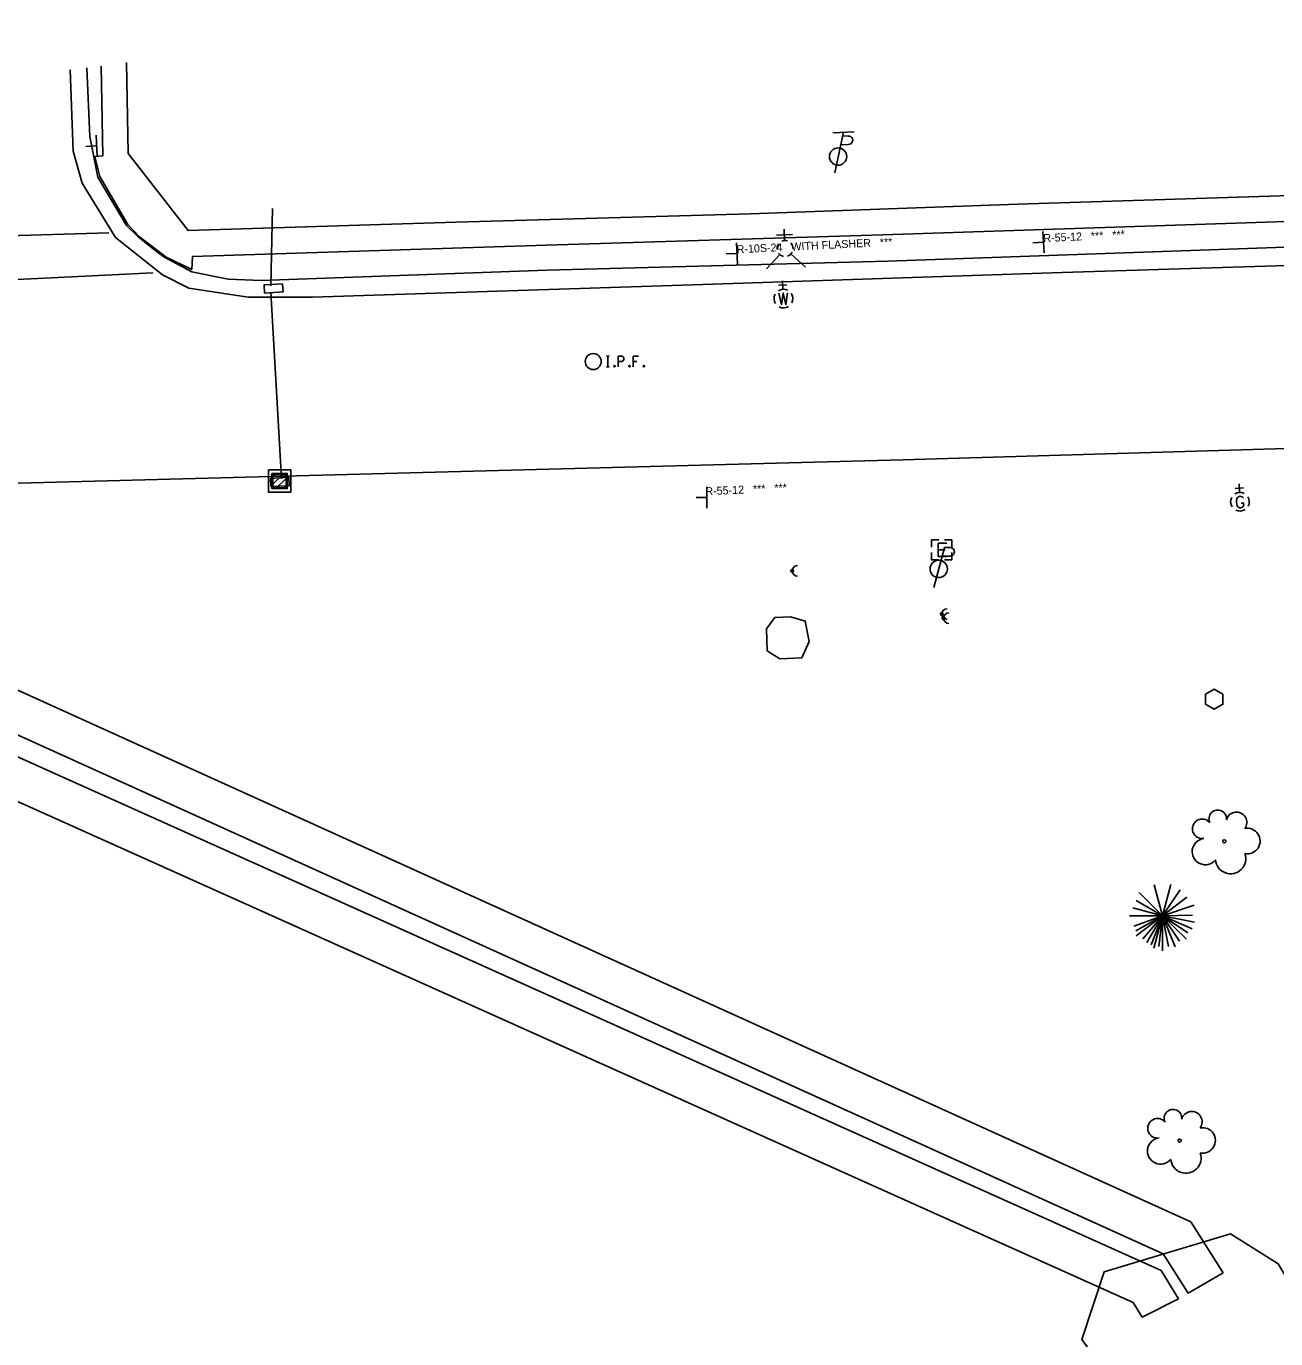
# Model space of a CAD drawing. Extents: x 129284 to 131418, y 268402 to 269012.
# Drawn here: x 129619.3 to 129806.6, y 268577.7 to 268774.5 of the extents above; entities that cross this region are included whole.
import ezdxf

# ---------------------------------------------------------------- set-up
doc = ezdxf.new("R2010")
doc.units = 0
for name, color, linetype in [('Default', 7, 'Continuous'), ('DR_X_Cells', 7, 'Continuous'), ('DR_X_Storm_Sewer', 7, 'Continuous'), ('GK_Drainage_Nodes', 7, 'Continuous'), ('Level 63', 7, 'Continuous'), ('PM_X_Crosswalk', 7, 'Continuous'), ('PV_X_Curb', 7, 'Continuous'), ('PV_X_EOP', 7, 'Continuous'), ('PV_X_Walk', 7, 'Continuous'), ('RD_X_Cells', 7, 'Continuous'), ('SN_X_Public', 7, 'Continuous'), ('SV_X_Mon_Cells_Found', 7, 'Continuous'), ('SV_X_Top_of_Bank', 7, 'Continuous'), ('UT_X_Electric_Cells', 7, 'Continuous'), ('UT_X_Gas', 7, 'Continuous'), ('UT_X_Misc_Cells', 7, 'Continuous'), ('VG_X_Cells', 7, 'Continuous')]:
    doc.layers.add(name, color=color, linetype=linetype)

# ---------------------------------------------------------------- blocks, each defined once
blk = doc.blocks.new('POINT_DISPLAY')
at = {"layer": 'Default'}
blk.add_line((0, 0), (0, 0), dxfattribs=at)

msp = doc.modelspace()

# ---------------------------------------------------------------- linework, layer by layer
at = {"layer": 'DR_X_Cells'}
for p, q in [((129656.14, 268705.67), (129657.9, 268707.43)), ((129656.14, 268706.8), (129656.77, 268707.43)), ((129656.74, 268705.14), (129658.43, 268706.83)), ((129657.87, 268705.14), (129658.43, 268705.7))]:
    msp.add_line(p, q, dxfattribs=at)
for points in [[(129655.62, 268707.95), (129658.95, 268707.95), (129658.95, 268704.61), (129655.62, 268704.61), (129655.62, 268707.95)], [(129656.14, 268707.43), (129658.43, 268707.43), (129658.43, 268705.14), (129656.14, 268705.14), (129656.14, 268707.43)], [(129656.29, 268707.28), (129658.29, 268707.28), (129658.29, 268705.28), (129656.29, 268705.28), (129656.29, 268707.28)]]:
    msp.add_lwpolyline(points, dxfattribs=at)
at = {"layer": 'DR_X_Storm_Sewer'}
for p, q in [((129602.83, 268681.77), (129793.89, 268595.19)), ((129789.73, 268590.4), (129598.55, 268677.03)), ((129597.05, 268674.32), (129789.44, 268587.88)), ((129785.23, 268583.1), (129592.78, 268669.57)), ((129793.89, 268595.19), (129798.76, 268587.53)), ((129793.49, 268584.48), (129789.73, 268590.4)), ((129789.44, 268587.88), (129792.03, 268583.64)), ((129798.76, 268587.53), (129793.49, 268584.48)), ((129786.59, 268580.89), (129785.23, 268583.1)), ((129792.03, 268583.64), (129786.59, 268580.89))]:
    msp.add_line(p, q, dxfattribs=at)
at = {"layer": 'PM_X_Crosswalk'}
for p, q in [((129596.24, 268742.49), (129631.69, 268743.48)), ((129638.28, 268737.49), (129590.12, 268735.16))]:
    msp.add_line(p, q, dxfattribs=at)
at = {"layer": 'PV_X_Curb'}
msp.add_lwpolyline([(129628.39, 268768.24), (129628.85, 268757.96), (129630.03, 268751.84), (129634.34, 268744.59), (129636.11, 268742.9), (129638.8, 268740.76), (129639.93, 268739.9), (129644.15, 268737.64), (129649.59, 268736.54), (129654.52, 268736.36), (129697.34, 268737.91), (129748.47, 268739.24), (129806.62, 268741.28), (129827.63, 268742.09), (129834.82, 268743.89), (129838.76, 268746.54), (129839.77, 268747.28), (129841.85, 268749.4), (129842.79, 268750.35), (129845.39, 268754.56), (129847.27, 268759.97), (129849.06, 268773.91)], dxfattribs=at)
at = {"layer": 'PV_X_EOP'}
msp.add_lwpolyline([(129851.57, 268773.49), (129849.39, 268758.43), (129846.3, 268751.07), (129843.04, 268746.84), (129839.56, 268743.92), (129834.27, 268741.14), (129825.93, 268739.15), (129774.6, 268737.57), (129719.24, 268735.72), (129662.21, 268733.87), (129652.57, 268733.86), (129643.67, 268735.18), (129639.72, 268737.19), (129632.68, 268742.79), (129627.69, 268750.93), (129626.36, 268755.75), (129625.89, 268767.95)], dxfattribs=at)
at = {"layer": 'PV_X_Walk'}
for p, q in [((129629.86, 268756.53), (129628.26, 268756.46)), ((129629.86, 268756.53), (129628.26, 268756.46)), ((129629.86, 268756.53), (129628.26, 268756.46)), ((129629.78, 268758.13), (129629.94, 268754.94)), ((129629.78, 268758.13), (129629.94, 268754.94)), ((129629.78, 268758.13), (129629.94, 268754.94)), ((129771.73, 268743.68), (129771.89, 268740.49)), ((129771.73, 268743.68), (129771.89, 268740.49)), ((129771.73, 268743.68), (129771.89, 268740.49)), ((129725.76, 268742.02), (129725.92, 268738.82)), ((129725.76, 268742.02), (129725.92, 268738.82)), ((129725.76, 268742.02), (129725.92, 268738.82)), ((129771.81, 268742.09), (129770.21, 268742.01)), ((129771.81, 268742.09), (129770.21, 268742.01)), ((129771.81, 268742.09), (129770.21, 268742.01)), ((129725.84, 268740.42), (129724.24, 268740.34)), ((129725.84, 268740.42), (129724.24, 268740.34)), ((129725.84, 268740.42), (129724.24, 268740.34))]:
    msp.add_line(p, q, dxfattribs=at)
for points in [[(129842.82, 268774.48), (129840.78, 268759.89), (129835, 268750.29), (129807.26, 268749.04), (129767.94, 268747.78), (129727.82, 268746.37), (129683.7, 268745.11), (129643.57, 268743.83), (129634.61, 268755.41), (129634.36, 268769.03)], [(129630.53, 268768.47), (129630.8, 268755.06), (129629.57, 268754.93), (129630.35, 268751.96), (129634.56, 268744.77), (129636.27, 268742.91), (129638.81, 268740.99), (129640.27, 268739.83), (129644.11, 268738.01), (129644.25, 268739.93), (129697.24, 268741.65), (129747.72, 268743.19), (129806.69, 268745.13), (129827.22, 268746.07), (129827.68, 268742.17)]]:
    msp.add_lwpolyline(points, dxfattribs=at)
at = {"layer": 'RD_X_Cells'}
for p, q in [((129743.4, 268758.66), (129740.21, 268758.5)), ((129741.81, 268758.58), (129740.5, 268752.51)), ((129741.4, 268756.68), (129742.59, 268756.74)), ((129741.68, 268757.97), (129742.52, 268758.02)), ((129734.16, 268743.26), (129731.76, 268743.15)), ((129733, 268742.35), (129732.91, 268744.06)), ((129732.26, 268740.26), (129730.28, 268738.08)), ((129733.95, 268740.34), (129736.13, 268738.37)), ((129733.35, 268735.71), (129732.08, 268735.64)), ((129732.75, 268735.04), (129732.69, 268736.31)), ((129801.8, 268705.24), (129800.53, 268705.17)), ((129801.19, 268704.57), (129801.13, 268705.84))]:
    msp.add_line(p, q, dxfattribs=at)
for points in [[(129732.14, 268734.43), (129732.55, 268732.72), (129732.78, 268734.46), (129733.18, 268732.75), (129733.42, 268734.49)], [(129801.46, 268702.96), (129801.81, 268702.98), (129801.82, 268702.63)], [(129730.36, 268680.84), (129730.29, 268684.14), (129731.54, 268685.81), (129733.89, 268685.94), (129736.09, 268685.29), (129736.69, 268682.24), (129735.56, 268679.76), (129732.29, 268679.64), (129730.36, 268680.84)], [(129796.11, 268672.8), (129797.41, 268672.05), (129798.7, 268672.8), (129798.7, 268674.3), (129797.41, 268675.05), (129796.11, 268674.3), (129796.11, 268672.8)]]:
    msp.add_lwpolyline(points, dxfattribs=at)
msp.add_circle((129741.02, 268754.94), 1.3, dxfattribs=at)
for centre, radius, start, end in [((129742.57, 268757.38), 0.638, 271.707, 93.9536), ((129733.06, 268741.14), 1.2, 142.8513, 186.8932), ((129733.06, 268741.14), 1.2, 70.9697, 114.8683), ((129733.06, 268741.14), 1.2, 286.6542, 332.7399), ((129733.06, 268741.14), 1.2, 358.8468, 42.8191), ((129733.06, 268741.14), 1.2, 214.709, 258.6782), ((129732.82, 268733.64), 1.4, 62.8486, 122.846), ((129732.82, 268733.64), 1.4, 152.8486, 212.8119), ((129732.82, 268733.64), 1.4, 332.8486, 32.8119), ((129732.82, 268733.64), 1.4, 242.8145, 302.8119), ((129801.26, 268703.17), 1.4, 152.8486, 212.8119), ((129801.26, 268703.17), 1.4, 62.8486, 122.846), ((129802.35, 268703.19), 1.62, 162.4251, 203.2354), ((129801.29, 268703.47), 0.528, 24.3704, 156.6885), ((129801.26, 268703.17), 1.4, 332.8486, 32.8119), ((129801.26, 268703.17), 1.4, 242.8145, 302.8119), ((129801.32, 268702.8), 0.528, 208.9721, 341.2901)]:
    msp.add_arc(centre, radius, start, end, dxfattribs=at)
at = {"layer": 'SN_X_Public'}
for p, q in [((129721.34, 268705.42), (129721.34, 268702.22)), ((129721.34, 268703.82), (129719.74, 268703.82))]:
    msp.add_line(p, q, dxfattribs=at)
at = {"layer": 'SV_X_Mon_Cells_Found'}
for points in [[(129706.32, 268725), (129706.67, 268725)], [(129706.5, 268723.4), (129706.5, 268725)], [(129708.06, 268723.4), (129708.06, 268725), (129708.59, 268725), (129708.65, 268724.98), (129708.72, 268724.96), (129708.76, 268724.93), (129708.79, 268724.91), (129708.83, 268724.84), (129708.87, 268724.78), (129708.89, 268724.68), (129708.89, 268724.53), (129708.88, 268724.48), (129708.86, 268724.4), (129708.81, 268724.31), (129708.77, 268724.28), (129708.73, 268724.25), (129708.68, 268724.23), (129708.59, 268724.21), (129708.06, 268724.21)], [(129711.07, 268725), (129710.31, 268725), (129710.31, 268723.4)], [(129706.32, 268723.4), (129706.67, 268723.4)], [(129707.46, 268723.61), (129707.51, 268723.61), (129707.54, 268723.58), (129707.58, 268723.53), (129707.58, 268723.47), (129707.54, 268723.42), (129707.51, 268723.4), (129707.46, 268723.4), (129707.42, 268723.42), (129707.39, 268723.47), (129707.39, 268723.53), (129707.42, 268723.58), (129707.46, 268723.61)], [(129709.7, 268723.61), (129709.76, 268723.61), (129709.79, 268723.58), (129709.83, 268723.53), (129709.83, 268723.47), (129709.79, 268723.42), (129709.76, 268723.4), (129709.7, 268723.4), (129709.67, 268723.42), (129709.64, 268723.47), (129709.64, 268723.53), (129709.67, 268723.58), (129709.7, 268723.61)], [(129710.31, 268724.21), (129710.85, 268724.21)], [(129711.85, 268723.61), (129711.91, 268723.61), (129711.94, 268723.58), (129711.98, 268723.53), (129711.98, 268723.47), (129711.94, 268723.42), (129711.91, 268723.4), (129711.85, 268723.4), (129711.82, 268723.42), (129711.79, 268723.47), (129711.79, 268723.53), (129711.82, 268723.58), (129711.85, 268723.61)]]:
    msp.add_lwpolyline(points, dxfattribs=at)
msp.add_circle((129704.31, 268724.2), 1.2, dxfattribs=at)
at = {"layer": 'SV_X_Top_of_Bank'}
msp.add_lwpolyline([(129845, 268530.21), (129829.61, 268548.57), (129818.87, 268569.2), (129807, 268588.91), (129799.86, 268593.38), (129780.88, 268587.69), (129777.57, 268577.53), (129789.72, 268560.83), (129808.83, 268530.7), (129820, 268513.76)], dxfattribs=at)
at = {"layer": 'UT_X_Electric_Cells'}
for p, q in [((129756.96, 268696.3), (129755.35, 268690.3)), ((129756.04, 268695.94), (129757.04, 268695.94)), ((129756.96, 268696.3), (129757.81, 268696.3)), ((129756.61, 268695.03), (129757.81, 268695.03))]:
    msp.add_line(p, q, dxfattribs=at)
for points in [[(129756.14, 268697.44), (129755.04, 268697.44), (129755.04, 268696.34)], [(129758.04, 268696.34), (129758.04, 268697.44), (129756.94, 268697.44)], [(129755.04, 268695.54), (129755.04, 268694.44), (129756.14, 268694.44)], [(129757.29, 268696.94), (129756.04, 268696.94), (129756.04, 268694.94), (129757.29, 268694.94)], [(129756.94, 268694.44), (129758.04, 268694.44), (129758.04, 268695.54)]]:
    msp.add_lwpolyline(points, dxfattribs=at)
msp.add_circle((129756.1, 268693.1), 1.3, dxfattribs=at)
msp.add_arc((129757.82, 268695.66), 0.638, 268.8767, 91.1233, dxfattribs=at)
at = {"layer": 'UT_X_Gas'}
msp.add_lwpolyline([(129879.52, 268712.49), (129869.17, 268712.98), (129750.71, 268709.45), (129606.76, 268705.66)], dxfattribs=at)
at = {"layer": 'UT_X_Misc_Cells'}
for centre in [(129734.12, 268692.82), (129756.57, 268686.34), (129756.82, 268685.71)]:
    msp.add_circle(centre, 0.2, dxfattribs=at)
for centre in [(129734.92, 268692.82), (129757.37, 268686.34), (129757.62, 268685.71)]:
    msp.add_arc(centre, 0.8, 90, 270, dxfattribs=at)
at = {"layer": 'VG_X_Cells'}
for p, q in [((129655.97, 268735.53), (129656.24, 268747.16)), ((129655.97, 268735.53), (129656.24, 268747.16)), ((129655.96, 268734.58), (129657.58, 268706.6)), ((129655.96, 268734.58), (129657.58, 268706.6)), ((129789.63, 268641.09), (129786.14, 268644.58)), ((129789.63, 268641.09), (129788.4, 268645.71)), ((129789.63, 268641.09), (129790.89, 268645.79)), ((129789.63, 268641.09), (129792.29, 268644.98)), ((129789.63, 268641.09), (129785.22, 268642.28)), ((129789.63, 268641.09), (129785.72, 268643.39)), ((129789.63, 268641.09), (129793.29, 268643.9)), ((129789.63, 268641.09), (129794.37, 268642.7)), ((129784.7, 268641.09), (129789.63, 268641.09)), ((129789.63, 268641.09), (129785.34, 268639.53)), ((129789.63, 268641.09), (129785.65, 268638.81)), ((129789.63, 268641.09), (129785.72, 268638.1)), ((129789.63, 268641.09), (129786.69, 268637.63)), ((129789.63, 268641.09), (129787.31, 268637.08)), ((129789.63, 268641.09), (129787.97, 268636.75)), ((129789.63, 268641.09), (129788.37, 268636.24)), ((129789.63, 268641.09), (129789.09, 268636.5)), ((129789.63, 268641.09), (129794.14, 268641.19)), ((129789.63, 268635.85), (129789.63, 268641.09)), ((129789.63, 268641.09), (129790.55, 268636.46)), ((129789.63, 268641.09), (129791.56, 268636.43)), ((129789.63, 268641.09), (129792.17, 268637.3)), ((129789.63, 268641.09), (129793.22, 268637.57)), ((129789.63, 268641.09), (129793.45, 268638.54)), ((129789.63, 268641.09), (129794.1, 268639.15)), ((129789.63, 268641.09), (129794.46, 268640.14))]:
    msp.add_line(p, q, dxfattribs=at)
for points in [[(129657.73, 268735.84), (129654.97, 268735.68), (129655.04, 268734.47), (129657.8, 268734.63), (129657.73, 268735.84)], [(129657.73, 268735.84), (129654.97, 268735.68), (129655.04, 268734.47), (129657.8, 268734.63), (129657.73, 268735.84)], [(129658.7, 268705.57), (129656, 268705.48), (129655.94, 268706.68), (129658.65, 268706.85), (129658.7, 268705.57)], [(129658.7, 268705.57), (129656, 268705.48), (129655.94, 268706.68), (129658.65, 268706.85), (129658.7, 268705.57)]]:
    msp.add_lwpolyline(points, dxfattribs=at)
for centre in [(129798.91, 268652.26), (129792.21, 268607.37)]:
    msp.add_circle(centre, 0.24, dxfattribs=at)
for centre, radius, start, end in [((129797.93, 268655.63), 1.32, 354.0047, 205.9741), ((129800.74, 268655.09), 1.55, 323.83, 165.0376), ((129795.6, 268654.13), 1.47, 39.0625, 279.5412), ((129802.37, 268652.3), 1.91, 259.1453, 101.4596), ((129796.06, 268650.71), 1.97, 96.1722, 320.5737), ((129799.86, 268649.66), 2.28, 184.9476, 19.4572), ((129788.9, 268609.23), 1.47, 39.0625, 279.5412), ((129791.22, 268610.74), 1.32, 354.0047, 205.9741), ((129794.03, 268610.2), 1.55, 323.83, 165.0376), ((129795.67, 268607.4), 1.91, 259.1453, 101.4596), ((129789.35, 268605.82), 1.97, 96.1722, 320.5737), ((129793.15, 268604.76), 2.28, 184.9476, 19.4572)]:
    msp.add_arc(centre, radius, start, end, dxfattribs=at)

# ---------------------------------------------------------------- block references
at = {"layer": 'GK_Drainage_Nodes', "xscale": 3.9370000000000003, "yscale": 3.9370000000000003}
for p in [(129657.29, 268707.95), (129657.29, 268707.28), (129656.29, 268706.28), (129657.29, 268706.28), (129657.29, 268706.28), (129657.29, 268706.28), (129657.29, 268705.28), (129658.29, 268706.28), (129657.29, 268704.61)]:
    msp.add_blockref('POINT_DISPLAY', p, dxfattribs=at)
at = {"layer": 'RD_X_Cells', "xscale": 3.9370000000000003, "yscale": 3.9370000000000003}
for p in [(129733.06, 268741.14), (129733.06, 268741.14), (129732.82, 268733.64), (129801.26, 268703.17)]:
    msp.add_blockref('POINT_DISPLAY', p, dxfattribs=at)
at = {"layer": 'UT_X_Electric_Cells', "xscale": 3.9370000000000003, "yscale": 3.9370000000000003}
msp.add_blockref('POINT_DISPLAY', (129756.54, 268695.94), dxfattribs=at)

# ---------------------------------------------------------------- texts
at = {"layer": 'Level 63'}
for s, p in [('R-10S-24   WITH FLASHER   ***', (129725.84, 268740.42)), ('R-10S-24   WITH FLASHER   ***', (129725.84, 268740.42)), ('R-55-12   ***   ***', (129771.81, 268742.09)), ('R-55-12   ***   ***', (129771.81, 268742.09)), ('R-55-12   ***   ***', (129721.15, 268704.13)), ('R-55-12   ***   ***', (129721.15, 268704.13))]:
    msp.add_text(s, height=1.2, rotation=2.8303, dxfattribs=at).set_placement(p)

doc.saveas('drawing.dxf')
